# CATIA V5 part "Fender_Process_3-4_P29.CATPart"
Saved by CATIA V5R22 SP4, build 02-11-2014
Part number: Fender
Bounding box of the stored display mesh (mm): x -850 to 46.495, y 0 to 122.298, z -30 to 626.626
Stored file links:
  C:\DATA\Car_ASSY\教育モデル\3_SOL\Fender_Process_3-64_P29.CATPart
  C:\DATA\Car_ASSY\教育モデル\3_SOL\Car_Fender.CATPart
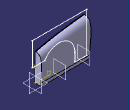
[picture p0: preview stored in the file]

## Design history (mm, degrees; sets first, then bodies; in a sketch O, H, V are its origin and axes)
Set1
  Plane1: type Offset, RefPlane yz-plane, Offset 400, reversed
  Plane2: type Offset, RefPlane Plane1, Offset 400, reversed
Body1 (main body)
Body2
  Sketch1 on yz-plane, origin (0, 0, 0), H (0, 1, 0), V (0, 0, 1)
    point P4 (100, 50)
    point P5 (10, 450)
    spline S1 through (10, 450) (100, 50)
    line L1 (0, 450) -> (10, 450)
    line L2 (0, 0) -> (0, 450)
    line L3 (100, 0) -> (0, 0)
    line L4 (100, 50) -> (100, 0)
    point P6 (100, 50)
    point P7 (10, 450)
    distance P4 L3 = 50
    distance P5 L2 = 10
    distance L4 L2 = 100
    distance L1 H = 450
    coincidence: L2 V, H L3, P4 P6, P7 P5
  Sketch2 on Plane1, origin (-400, 0, 0), H (0, 1, 0), V (0, 0, 1)
    point P4 (100, 50)
    point P5 (10, 530)
    spline S1 through (10, 530) (100, 50)
    line L1 (0, 530) -> (10, 530)
    line L2 (0, 0) -> (0, 530)
    line L3 (100, 0) -> (0, 0)
    line L4 (100, 50) -> (100, 0)
    point P6 (100, 50)
    point P7 (10, 530)
    distance P4 L3 = 50
    distance P5 L2 = 10
    distance L4 L2 = 100
    distance L1 H = 530
    coincidence: L2 V, H L3, P4 P6, P7 P5
  Sketch3 on Plane2, origin (-800, 0, 0), H (0, 1, 0), V (0, 0, 1)
    point P4 (100, 50)
    point P5 (10, 580)
    spline S1 through (10, 580) (100, 50)
    line L1 (0, 580) -> (10, 580)
    line L2 (0, 0) -> (0, 580)
    line L3 (100, 0) -> (0, 0)
    line L4 (100, 50) -> (100, 0)
    point P6 (100, 50)
    point P7 (10, 580)
    distance P4 L3 = 50
    distance P5 L2 = 10
    distance L4 L2 = 100
    distance L1 H = 580
    coincidence: L2 V, H L3, P4 P6, P7 P5
  Loft1: solid, Sections (Sketch1; Sketch2; Sketch3)
Body3
  Sketch4 on zx-plane, origin (0, 0, 0), H (-1, 0, 0), V (0, 0, 1)
    line L1 (-46.4952, 240) -> (159.0779, 240)
    arc A1 centre (390, 110) radius 265 from (159.0779, 240) to (655, 109.9999) cw
    point P2 (390, 110)
    line L2 (655, 109.9999) -> (655, -30)
    line L3 (-46.4952, 626.6258) -> (850, 626.6258)
    line L4 (850, 626.6258) -> (850, -30)
    line L5 (850, -30) -> (655, -30)
    line L6 (-46.4952, 626.6258) -> (-46.4952, 240)
    radius A1 = 265
    distance P2 H = 110
    distance V P2 = 390
    distance H L1 = 240
    horizontal: L1 H, L3 H, L5 H
    tangency: L2 A1
    vertical: L2 V, L4 V, L6 V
